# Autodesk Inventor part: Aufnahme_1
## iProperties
Created: 2008-11
Part Number: Aufnahme_1
Project: Anlage
Material: Kunststoff  (grün)
Description: Leiste
Document SubType Name: Modellieren
Designer: GEIKON
Manufacturer: Standard
Standards Organization: Custom
Mass: 10020.2 g
Surface Area: 3836.51 cm^2
Volume: 10020.2 cm^3
Density: 1 g/cm^3
Author: GEIKON
Revision Number: 00
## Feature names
1. Extrusion5
2. Extrusion6
